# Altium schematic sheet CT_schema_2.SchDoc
size 362 x 192 mm
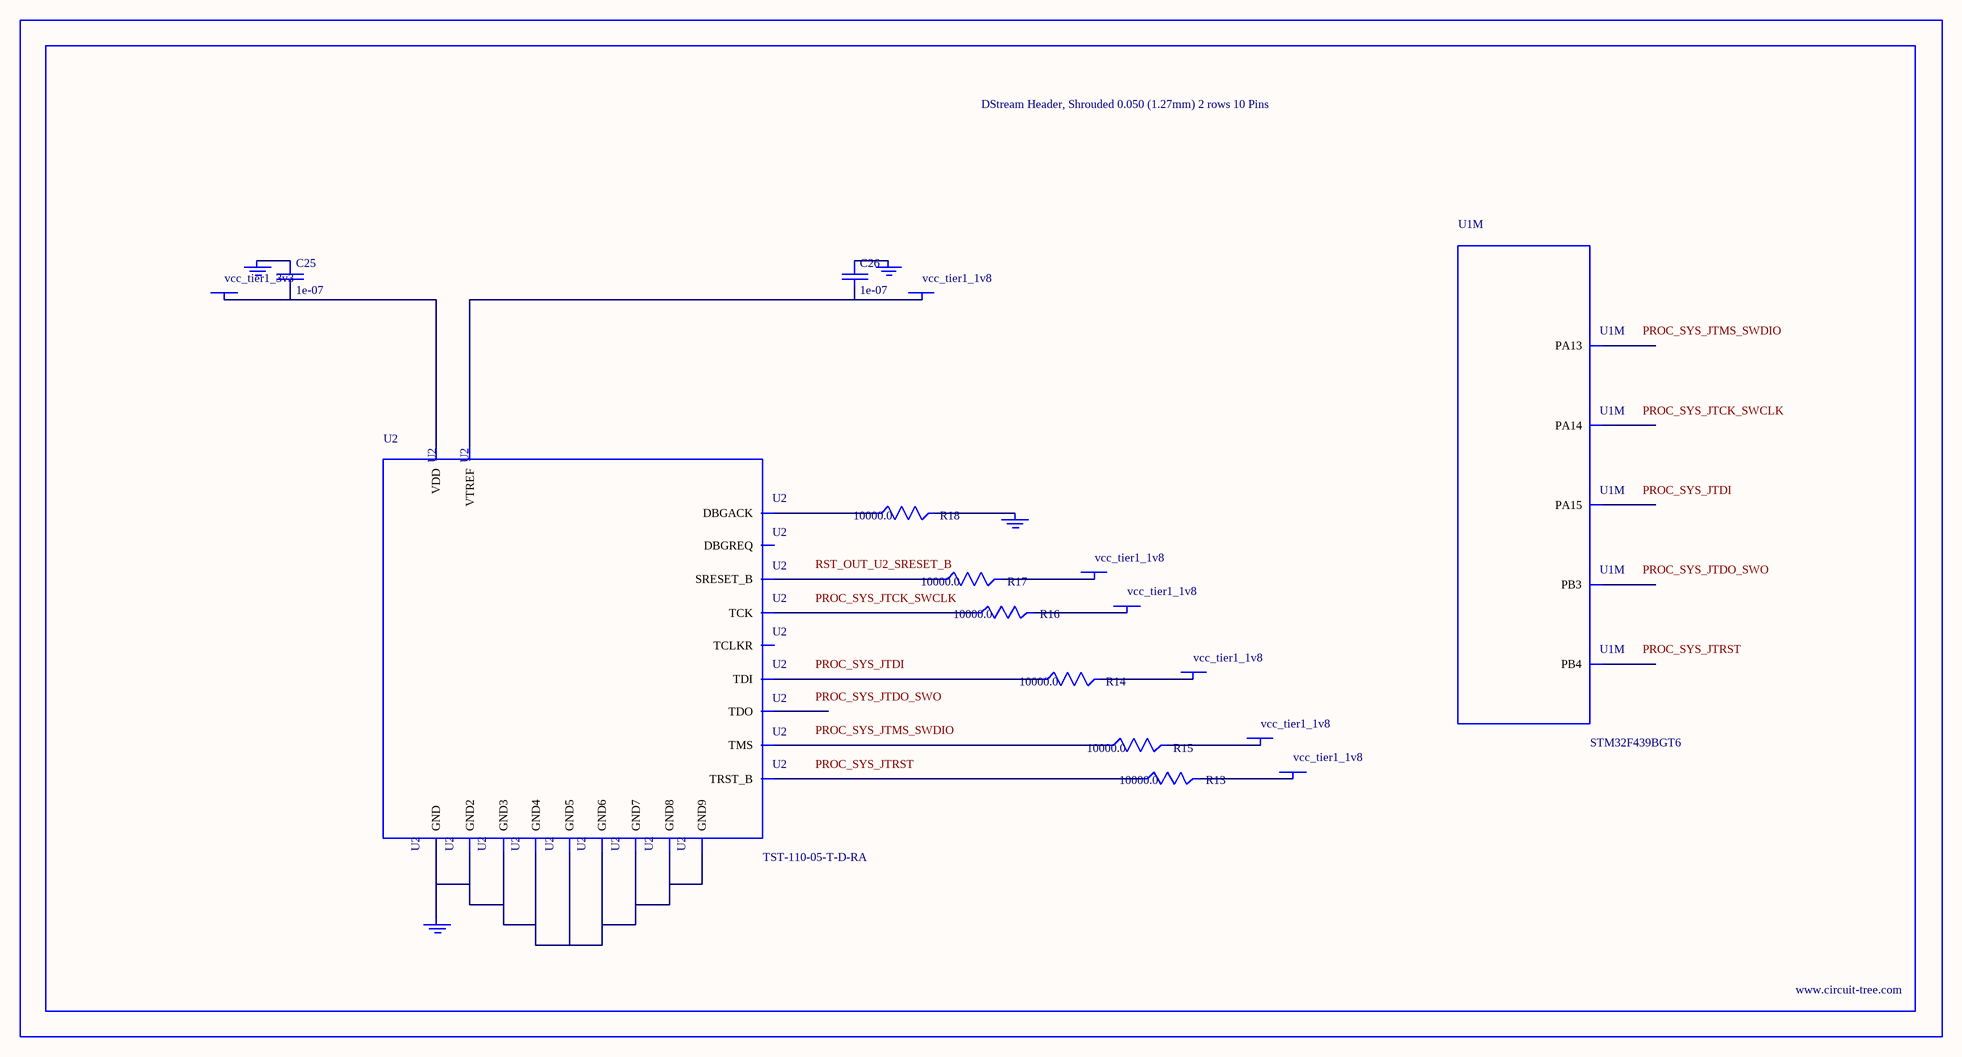
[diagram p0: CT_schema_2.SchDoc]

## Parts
BORDER1  (no value)
C25  1e-07  [C0402]
C26  1e-07  [C0402]
GND_INSTANCE_1_0  (no value)
GND_INSTANCE_1_1  (no value)
GND_INSTANCE_1_2  (no value)
GND_INSTANCE_1_3  (no value)
POWER_INSTANCE_1_0  vcc_tier1_1v8
POWER_INSTANCE_1_1  vcc_tier1_3v3
POWER_INSTANCE_1_2  vcc_tier1_1v8
POWER_INSTANCE_1_3  vcc_tier1_1v8
POWER_INSTANCE_1_4  vcc_tier1_1v8
POWER_INSTANCE_1_5  vcc_tier1_1v8
POWER_INSTANCE_1_6  vcc_tier1_1v8
R13  10000.0  [R0603]
R14  10000.0  [R0603]
R15  10000.0  [R0603]
R16  10000.0  [R0603]
R17  10000.0  [R0603]
R18  10000.0  [R0603]
U1  STM32F439BGT6  [LQFP208]  (part M of 18)
U2  TST-110-05-T-D-RA  [TST-110-05-T-D-RA]

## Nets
NetC25_1: C25.1 GND_INSTANCE_1_1.0(GND)
NetC25_2: C25.2 POWER_INSTANCE_1_1.0(PWR) U2.2(VDD)
NetC26_1: C26.1 GND_INSTANCE_1_0.0(GND)
NetC26_2: C26.2 POWER_INSTANCE_1_0.0(PWR) U2.1(VTREF)
NetGND_INSTANCE_1_2_0: GND_INSTANCE_1_2.0(GND) R18.2
NetGND_INSTANCE_1_3_0: GND_INSTANCE_1_3.0(GND) U2.4(GND) U2.6(GND2) U2.8(GND3) U2.10(GND4) U2.12(GND5) U2.14(GND6) U2.16(GND7) U2.18(GND8) U2.20(GND9)
NetPOWER_INSTANCE_1_2_0: POWER_INSTANCE_1_2.0(PWR) R13.2
NetPOWER_INSTANCE_1_3_0: POWER_INSTANCE_1_3.0(PWR) R14.2
NetPOWER_INSTANCE_1_4_0: POWER_INSTANCE_1_4.0(PWR) R15.2
NetPOWER_INSTANCE_1_5_0: POWER_INSTANCE_1_5.0(PWR) R16.2
NetPOWER_INSTANCE_1_6_0: POWER_INSTANCE_1_6.0(PWR) R17.2
NetR13_1: R13.1 U2.3(TRST_B)
NetR14_1: R14.1 U2.5(TDI)
NetR15_1: R15.1 U2.7(TMS)
NetR16_1: R16.1 U2.9(TCK)
NetR17_1: R17.1 U2.15(SRESET_B)
NetR18_1: R18.1 U2.19(DBGACK)

Not connected (* = marked no-connect by the designer): U1 147(PA13) 159(PA14) 160(PA15) 192(PB3) 193(PB4); U2 11(TCLKR) 13(TDO) 17(DBGREQ)

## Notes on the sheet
- Labels drawn without touching a wire or pin: PROC_SYS_JTCK_SWCLK, PROC_SYS_JTDI, PROC_SYS_JTDO_SWO, PROC_SYS_JTMS_SWDIO, PROC_SYS_JTRST, RST_OUT_U2_SRESET_B

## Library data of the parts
BORDER1 = BORDER_PAGE1
C25 C26 = C0402C104K3RACTU
GND_INSTANCE_1_0-GND_INSTANCE_1_3 = GND
POWER_INSTANCE_1_0-POWER_INSTANCE_1_6 = PWR
R13-R18 = RC0603JR-0710KL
